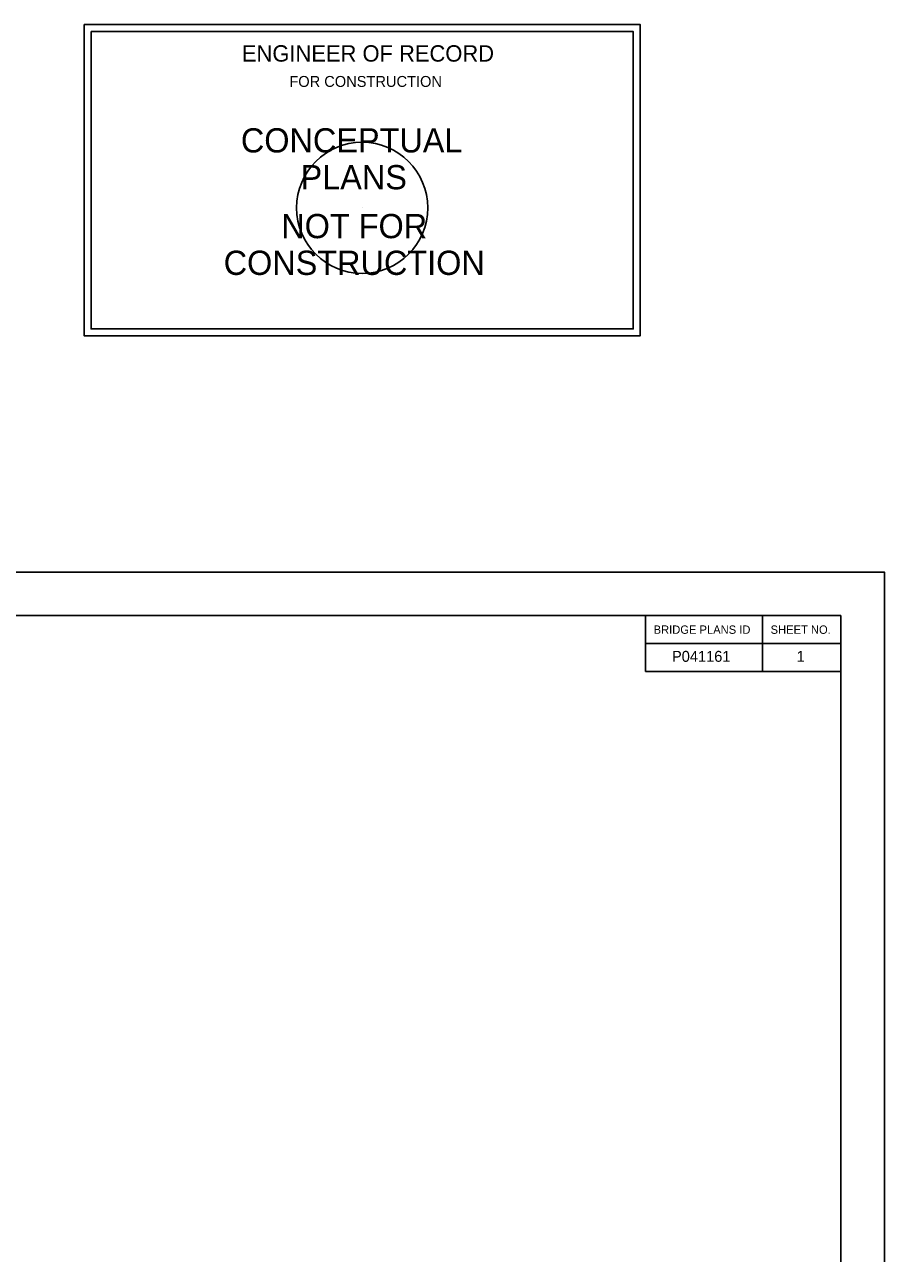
# Model space of a CAD drawing. Extents: x -2.83 to 3.9, y -2.5 to 2.32.
# Drawn here: x 2.18 to 3, y -1.316 to -0.145 of the extents above; entities that cross this region are included whole.
import ezdxf

# ---------------------------------------------------------------- set-up
doc = ezdxf.new("R2010")
doc.units = 0
for name, color, linetype in [('BR_AUTO DIMENSION', 7, 'Continuous'), ('BR_BORDER LINES', 7, 'Continuous'), ('BR_DETAILS', 7, 'Continuous'), ('Default', 7, 'Continuous'), ('NoPlot', 7, 'Continuous')]:
    doc.layers.add(name, color=color, linetype=linetype)

msp = doc.modelspace()

# ---------------------------------------------------------------- linework, layer by layer
at = {"layer": 'BR_BORDER LINES'}
for p, q in [((0.1667, -0.7082), (2.9583, -0.7082)), ((2.7722, -0.7614), (2.7722, -0.7083)), ((2.8837, -0.7614), (2.8837, -0.7083)), ((2.9583, -2.4582), (2.9583, -0.7082)), ((2.7722, -0.7349), (2.9583, -0.7349)), ((2.7722, -0.7614), (2.9583, -0.7614)), ((2.9583, -1.3928), (2.9583, -0.8053))]:
    msp.add_line(p, q, dxfattribs=at)
at = {"layer": 'BR_DETAILS'}
for points in [[(2.2372, -0.1449), (2.7672, -0.1449), (2.7672, -0.4415), (2.2372, -0.4415)], [(2.2439, -0.1515), (2.7606, -0.1515), (2.7606, -0.4349), (2.2439, -0.4349)]]:
    msp.add_lwpolyline(points, close=True, dxfattribs=at)
at = {"layer": 'Default'}
msp.add_line((2.921, -0.7481), (2.921, -0.7481), dxfattribs=at)
msp.add_line((2.921, -0.7481), (2.921, -0.7481), dxfattribs=at)
at = {"layer": 'NoPlot'}
msp.add_line((2.5022, -0.3196), (2.5022, -0.3196), dxfattribs=at)
msp.add_lwpolyline([(0, -0.6667), (3, -0.6667), (3, -2.5), (0, -2.5)], close=True, dxfattribs=at)
msp.add_circle((2.5022, -0.3196), 0.0625, dxfattribs=at)

# ---------------------------------------------------------------- texts
at = {"layer": 'BR_AUTO DIMENSION'}
for s, height, p in [('P041161', 0.01042, (2.7975, -0.7523)), ('1', 0.0104, (2.9163, -0.7523))]:
    msp.add_text(s, height=height, dxfattribs=at).set_placement(p)
at = {"layer": 'BR_DETAILS'}
for s, height, p in [('CONCEPTUAL', 0.02311, (2.3866, -0.2668)), ('PLANS', 0.02311, (2.4435, -0.3019)), ('NOT FOR', 0.02311, (2.4251, -0.3485)), ('CONSTRUCTION', 0.023108, (2.3702, -0.3835)), ('BRIDGE PLANS ID', 0.007961, (2.78, -0.7256)), ('SHEET NO.', 0.00796, (2.8915, -0.7256))]:
    msp.add_text(s, height=height, rotation=360, dxfattribs=at).set_placement(p)
at = {"layer": 'Default'}
for s, height, p in [('ENGINEER OF RECORD', 0.015625, (2.3876, -0.1802)), ('FOR CONSTRUCTION', 0.010417, (2.4328, -0.2043))]:
    msp.add_text(s, height=height, dxfattribs=at).set_placement(p)

doc.saveas('drawing.dxf')
